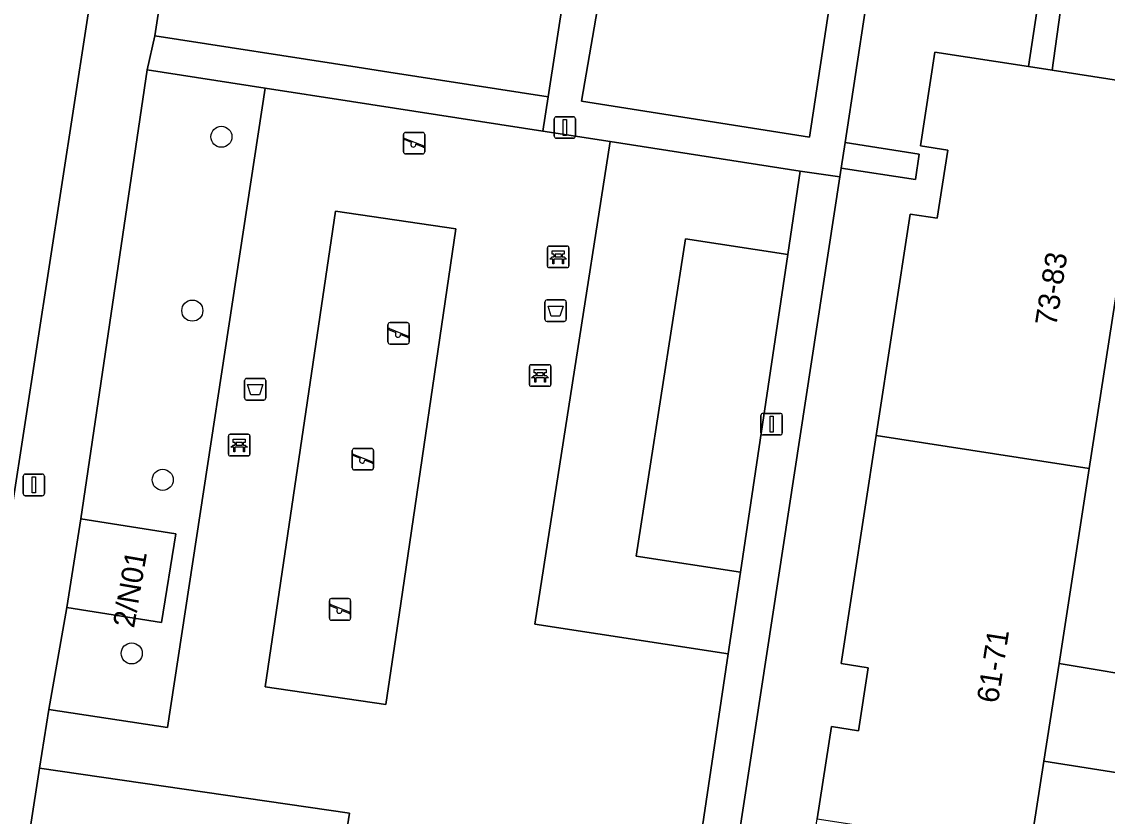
# Model space of a CAD drawing. Extents: x 161084 to 161928, y 385354 to 386522.
# Drawn here: x 161669.4 to 161719.8, y 385529 to 385565.9 of the extents above; entities that cross this region are included whole.
import ezdxf

# ---------------------------------------------------------------- set-up
doc = ezdxf.new("R2010")
doc.units = 0
for name, color, linetype in [('IMGEO_Afvalbak', 7, 'Continuous'), ('IMGEO_Bank', 7, 'Continuous'), ('IMGEO_Boom', 7, 'Continuous'), ('IMGEO_Groenvoorziening', 7, 'Continuous'), ('IMGEO_Lichtmast', 7, 'Continuous'), ('IMGEO_Pand', 7, 'Continuous'), ('IMGEO_Pand_nummerreeks', 7, 'Continuous'), ('IMGEO_Speelvoorziening', 7, 'Continuous'), ('IMGEO_Terreindeel_zand', 7, 'Continuous'), ('IMGEO_Voetpad_open', 7, 'Continuous')]:
    doc.layers.add(name, color=color, linetype=linetype)

msp = doc.modelspace()

# ---------------------------------------------------------------- linework, layer by layer
at = {"layer": 'IMGEO_Afvalbak'}
for p, q in [((161693.674, 385552.093), (161693.674, 385552.893)), ((161693.674, 385552.893), (161693.674, 385552.093)), ((161693.774, 385552.993), (161694.564, 385552.993)), ((161694.564, 385552.993), (161693.774, 385552.993)), ((161694.664, 385552.893), (161694.664, 385552.093)), ((161694.664, 385552.093), (161694.664, 385552.893)), ((161694.564, 385551.993), (161693.774, 385551.993)), ((161693.774, 385551.993), (161694.564, 385551.993)), ((161679.82, 385549.344), (161680.61, 385549.344)), ((161680.61, 385549.344), (161679.82, 385549.344)), ((161679.72, 385548.444), (161679.72, 385549.244)), ((161679.72, 385549.244), (161679.72, 385548.444)), ((161680.71, 385549.244), (161680.71, 385548.444)), ((161680.71, 385548.444), (161680.71, 385549.244)), ((161680.61, 385548.344), (161679.82, 385548.344)), ((161679.82, 385548.344), (161680.61, 385548.344))]:
    msp.add_line(p, q, dxfattribs=at)
for points in [[(161693.817, 385552.707), (161694.521, 385552.707), (161694.372, 385552.237), (161693.966, 385552.237), (161693.817, 385552.707)], [(161679.863, 385549.058), (161680.567, 385549.058), (161680.418, 385548.588), (161680.012, 385548.588), (161679.863, 385549.058)]]:
    msp.add_lwpolyline(points, dxfattribs=at)
for centre, start, end in [((161693.774, 385552.893), 90, 180), ((161693.774, 385552.893), 90, 180), ((161694.564, 385552.893), 0, 90), ((161694.564, 385552.893), 360, 90), ((161693.774, 385552.093), 180, 270), ((161693.774, 385552.093), 180, 270), ((161694.564, 385552.093), 270, 0), ((161694.564, 385552.093), 270, 0), ((161679.82, 385549.244), 90, 180), ((161679.82, 385549.244), 90, 180), ((161680.61, 385549.244), 0, 90), ((161680.61, 385549.244), 360, 90), ((161679.82, 385548.444), 180, 270), ((161679.82, 385548.444), 180, 270), ((161680.61, 385548.444), 270, 0), ((161680.61, 385548.444), 270, 0)]:
    msp.add_arc(centre, 0.1, start, end, dxfattribs=at)
at = {"layer": 'IMGEO_Bank'}
for p, q in [((161693.788, 385554.564), (161693.788, 385555.405)), ((161693.788, 385555.405), (161693.788, 385554.564)), ((161693.863, 385555.489), (161694.704, 385555.489)), ((161694.704, 385555.489), (161693.863, 385555.489)), ((161694.788, 385555.414), (161694.788, 385554.573)), ((161694.788, 385554.573), (161694.788, 385555.414)), ((161694.485, 385554.887), (161694.092, 385554.887)), ((161694.097, 385554.995), (161694.097, 385555.101)), ((161694.141, 385555.101), (161694.141, 385554.995)), ((161694.429, 385555.107), (161694.147, 385555.107)), ((161694.147, 385554.989), (161694.429, 385554.989)), ((161694.435, 385554.995), (161694.435, 385555.101)), ((161694.479, 385555.101), (161694.479, 385554.995)), ((161694.713, 385554.489), (161693.872, 385554.489)), ((161693.872, 385554.489), (161694.713, 385554.489)), ((161692.95, 385549.057), (161692.95, 385549.898)), ((161692.95, 385549.898), (161692.95, 385549.057)), ((161693.025, 385549.982), (161693.866, 385549.982)), ((161693.866, 385549.982), (161693.025, 385549.982)), ((161693.95, 385549.907), (161693.95, 385549.066)), ((161693.95, 385549.066), (161693.95, 385549.907)), ((161693.647, 385549.38), (161693.254, 385549.38)), ((161693.259, 385549.488), (161693.259, 385549.594)), ((161693.303, 385549.594), (161693.303, 385549.488)), ((161693.591, 385549.6), (161693.309, 385549.6)), ((161693.309, 385549.482), (161693.591, 385549.482)), ((161693.597, 385549.488), (161693.597, 385549.594)), ((161693.641, 385549.594), (161693.641, 385549.488)), ((161693.875, 385548.982), (161693.034, 385548.982)), ((161693.034, 385548.982), (161693.875, 385548.982)), ((161678.973, 385545.829), (161678.973, 385546.67)), ((161678.973, 385546.67), (161678.973, 385545.829)), ((161679.048, 385546.754), (161679.889, 385546.754)), ((161679.889, 385546.754), (161679.048, 385546.754)), ((161679.282, 385546.26), (161679.282, 385546.366)), ((161679.326, 385546.366), (161679.326, 385546.26)), ((161679.614, 385546.372), (161679.332, 385546.372)), ((161679.62, 385546.26), (161679.62, 385546.366)), ((161679.664, 385546.366), (161679.664, 385546.26)), ((161679.973, 385546.679), (161679.973, 385545.838)), ((161679.973, 385545.838), (161679.973, 385546.679)), ((161679.67, 385546.152), (161679.277, 385546.152)), ((161679.332, 385546.254), (161679.614, 385546.254)), ((161679.898, 385545.754), (161679.057, 385545.754)), ((161679.057, 385545.754), (161679.898, 385545.754))]:
    msp.add_line(p, q, dxfattribs=at)
for points in [[(161694.035, 385554.887), (161693.893, 385554.887), (161694.005, 385554.989), (161694.091, 385554.989)], [(161694.091, 385555.107), (161694.005, 385555.107), (161694.005, 385555.268), (161694.568, 385555.268), (161694.568, 385555.107), (161694.485, 385555.107)], [(161694.485, 385554.989), (161694.568, 385554.989), (161694.68, 385554.887), (161694.541, 385554.887)], [(161694.085, 385554.88), (161694.085, 385554.673), (161694.042, 385554.673), (161694.042, 385554.88)], [(161694.535, 385554.88), (161694.535, 385554.673), (161694.491, 385554.673), (161694.491, 385554.88)], [(161693.197, 385549.38), (161693.055, 385549.38), (161693.167, 385549.482), (161693.253, 385549.482)], [(161693.253, 385549.6), (161693.167, 385549.6), (161693.167, 385549.761), (161693.73, 385549.761), (161693.73, 385549.6), (161693.647, 385549.6)], [(161693.247, 385549.373), (161693.247, 385549.166), (161693.204, 385549.166), (161693.204, 385549.373)], [(161693.647, 385549.482), (161693.73, 385549.482), (161693.842, 385549.38), (161693.703, 385549.38)], [(161693.697, 385549.373), (161693.697, 385549.166), (161693.653, 385549.166), (161693.653, 385549.373)], [(161679.276, 385546.372), (161679.19, 385546.372), (161679.19, 385546.533), (161679.753, 385546.533), (161679.753, 385546.372), (161679.67, 385546.372)], [(161679.22, 385546.152), (161679.078, 385546.152), (161679.19, 385546.254), (161679.276, 385546.254)], [(161679.27, 385546.145), (161679.27, 385545.938), (161679.227, 385545.938), (161679.227, 385546.145)], [(161679.67, 385546.254), (161679.753, 385546.254), (161679.865, 385546.152), (161679.726, 385546.152)], [(161679.72, 385546.145), (161679.72, 385545.938), (161679.676, 385545.938), (161679.676, 385546.145)]]:
    msp.add_lwpolyline(points, dxfattribs=at)
for centre, radius, start, end in [((161693.866, 385555.411), 0.0779, 92.4484, 184.2845), ((161693.866, 385555.411), 0.0779, 92.4484, 184.2845), ((161694.71, 385555.411), 0.0779, 2.4484, 94.2845), ((161694.71, 385555.411), 0.0779, 2.4484, 94.2845), ((161694.035, 385554.88), 0.00671, 2.8957, 87.1043), ((161694.092, 385554.88), 0.00671, 92.8957, 177.1043), ((161694.09, 385555.1), 0.00671, 2.8957, 87.1043), ((161694.09, 385554.996), 0.00671, 272.8957, 357.1043), ((161694.147, 385555.1), 0.00671, 92.8957, 177.1043), ((161694.147, 385554.996), 0.00671, 182.8957, 267.1043), ((161694.429, 385555.1), 0.00671, 2.8957, 87.1043), ((161694.429, 385554.996), 0.00671, 272.8957, 357.1043), ((161694.486, 385555.1), 0.00671, 92.8957, 177.1043), ((161694.486, 385554.996), 0.00671, 182.8957, 267.1043), ((161694.484, 385554.88), 0.00671, 2.8957, 87.1043), ((161694.541, 385554.88), 0.00671, 92.8957, 177.1043), ((161693.866, 385554.567), 0.0779, 182.4484, 274.2845), ((161693.866, 385554.567), 0.0779, 182.4484, 274.2845), ((161694.71, 385554.567), 0.0779, 272.4484, 4.2845), ((161694.71, 385554.567), 0.0779, 272.4484, 4.2845), ((161693.028, 385549.904), 0.0779, 92.4484, 184.2845), ((161693.028, 385549.904), 0.0779, 92.4484, 184.2845), ((161693.872, 385549.904), 0.0779, 2.4484, 94.2845), ((161693.872, 385549.904), 0.0779, 2.4484, 94.2845), ((161693.197, 385549.373), 0.00671, 2.8957, 87.1043), ((161693.254, 385549.373), 0.00671, 92.8957, 177.1043), ((161693.252, 385549.593), 0.00671, 2.8957, 87.1043), ((161693.252, 385549.489), 0.00671, 272.8957, 357.1043), ((161693.309, 385549.593), 0.00671, 92.8957, 177.1043), ((161693.309, 385549.489), 0.00671, 182.8957, 267.1043), ((161693.591, 385549.593), 0.00671, 2.8957, 87.1043), ((161693.591, 385549.489), 0.00671, 272.8957, 357.1043), ((161693.648, 385549.593), 0.00671, 92.8957, 177.1043), ((161693.648, 385549.489), 0.00671, 182.8957, 267.1043), ((161693.646, 385549.373), 0.00671, 2.8957, 87.1043), ((161693.703, 385549.373), 0.00671, 92.8957, 177.1043), ((161693.028, 385549.06), 0.0779, 182.4484, 274.2845), ((161693.028, 385549.06), 0.0779, 182.4484, 274.2845), ((161693.872, 385549.06), 0.0779, 272.4484, 4.2845), ((161693.872, 385549.06), 0.0779, 272.4484, 4.2845), ((161679.051, 385546.676), 0.0779, 92.4484, 184.2845), ((161679.051, 385546.676), 0.0779, 92.4484, 184.2845), ((161679.275, 385546.365), 0.00671, 2.8957, 87.1043), ((161679.332, 385546.365), 0.00671, 92.8957, 177.1043), ((161679.614, 385546.365), 0.00671, 2.8957, 87.1043), ((161679.671, 385546.365), 0.00671, 92.8957, 177.1043), ((161679.895, 385546.676), 0.0779, 2.4484, 94.2845), ((161679.895, 385546.676), 0.0779, 2.4484, 94.2845), ((161679.051, 385545.832), 0.0779, 182.4484, 274.2845), ((161679.051, 385545.832), 0.0779, 182.4484, 274.2845), ((161679.22, 385546.145), 0.00671, 2.8957, 87.1043), ((161679.277, 385546.145), 0.00671, 92.8957, 177.1043), ((161679.275, 385546.261), 0.00671, 272.8957, 357.1043), ((161679.332, 385546.261), 0.00671, 182.8957, 267.1043), ((161679.614, 385546.261), 0.00671, 272.8957, 357.1043), ((161679.671, 385546.261), 0.00671, 182.8957, 267.1043), ((161679.669, 385546.145), 0.00671, 2.8957, 87.1043), ((161679.726, 385546.145), 0.00671, 92.8957, 177.1043), ((161679.895, 385545.832), 0.0779, 272.4484, 4.2845), ((161679.895, 385545.832), 0.0779, 272.4484, 4.2845)]:
    msp.add_arc(centre, radius, start, end, dxfattribs=at)
at = {"layer": 'IMGEO_Boom'}
for centre in [(161678.648, 385560.563), (161677.296, 385552.493), (161675.921, 385544.64), (161674.481, 385536.583)]:
    msp.add_circle(centre, 0.489, dxfattribs=at)
at = {"layer": 'IMGEO_Groenvoorziening'}
for points in [[(161676.732, 385572.916), (161675.558, 385565.255), (161684.945, 385563.794), (161686.427, 385563.563), (161693.826, 385562.411), (161695.311, 385572.063), (161695.631, 385574.145), (161695.859, 385575.628), (161698.823, 385594.901), (161698.975, 385595.889), (161700.619, 385606.575)], [(161662.849, 385544.418), (161663.304, 385544.268), (161668.139, 385543.516), (161668.928, 385543.394), (161672.366, 385565.674), (161674.034, 385576.484)], [(161727.809, 385567.017), (161717.914, 385568.577), (161717.223, 385563.649), (161721.705, 385562.959)], [(161723.62, 385530.521), (161716.851, 385531.587), (161716.2, 385527.382), (161715.451, 385522.539), (161722.403, 385521.5), (161723.407, 385522.236), (161724.441, 385529.408)]]:
    msp.add_lwpolyline(points, dxfattribs=at)
for points in [[(161707.395, 385570.046), (161696.989, 385571.64), (161695.367, 385562.217), (161705.954, 385560.553)], [(161708.692, 385535.916), (161707.425, 385536.11), (161709.051, 385546.696), (161710.63, 385556.976), (161711.897, 385556.782), (161712.382, 385559.945), (161711.116, 385560.139), (161711.784, 385564.487), (161716.127, 385563.818), (161716.872, 385568.738), (161709.056, 385569.786), (161707.615, 385560.292), (161711.058, 385559.763), (161710.876, 385558.577), (161707.433, 385559.106), (161707.374, 385558.705), (161702.137, 385524.559), (161705.558, 385523.963), (161706.317, 385528.904), (161706.975, 385533.185), (161708.242, 385532.991)], [(161670.626, 385533.985), (161676.151, 385533.143), (161680.682, 385562.825), (161675.205, 385563.675), (161672.117, 385542.833), (161676.525, 385542.134), (161675.871, 385538.012), (161671.463, 385538.711)], [(161702.756, 385540.358), (161697.915, 385541.104), (161700.208, 385555.827), (161704.956, 385555.095), (161705.534, 385558.969), (161696.695, 385560.34), (161693.207, 385537.945), (161702.189, 385536.561)], [(161702.756, 385540.358), (161704.956, 385555.095), (161700.208, 385555.827), (161697.915, 385541.104)], [(161717.551, 385536.113), (161722.189, 385535.345), (161724.894, 385553.02), (161720.279, 385553.742), (161718.953, 385545.171)], [(161668.88, 385522.726), (161683.871, 385520.546), (161684.952, 385527.492), (161684.345, 385527.588), (161684.594, 385529.164), (161670.203, 385531.256)]]:
    msp.add_lwpolyline(points, close=True, dxfattribs=at)
at = {"layer": 'IMGEO_Lichtmast'}
for p, q in [((161694.202, 385561.495), (161694.992, 385561.495)), ((161694.992, 385561.495), (161694.202, 385561.495)), ((161694.102, 385560.595), (161694.102, 385561.395)), ((161694.102, 385561.395), (161694.102, 385560.595)), ((161695.092, 385561.395), (161695.092, 385560.595)), ((161695.092, 385560.595), (161695.092, 385561.395)), ((161694.992, 385560.495), (161694.202, 385560.495)), ((161694.202, 385560.495), (161694.992, 385560.495)), ((161703.707, 385546.827), (161703.707, 385547.627)), ((161703.707, 385547.627), (161703.707, 385546.827)), ((161703.807, 385547.727), (161704.597, 385547.727)), ((161704.597, 385547.727), (161703.807, 385547.727)), ((161704.697, 385547.627), (161704.697, 385546.827)), ((161704.697, 385546.827), (161704.697, 385547.627)), ((161704.597, 385546.727), (161703.807, 385546.727)), ((161703.807, 385546.727), (161704.597, 385546.727)), ((161669.44, 385544.005), (161669.44, 385544.805)), ((161669.44, 385544.805), (161669.44, 385544.005)), ((161669.54, 385544.905), (161670.33, 385544.905)), ((161670.33, 385544.905), (161669.54, 385544.905)), ((161670.43, 385544.805), (161670.43, 385544.005)), ((161670.43, 385544.005), (161670.43, 385544.805)), ((161670.33, 385543.905), (161669.54, 385543.905)), ((161669.54, 385543.905), (161670.33, 385543.905))]:
    msp.add_line(p, q, dxfattribs=at)
for points in [[(161694.522, 385561.37), (161694.672, 385561.37), (161694.672, 385560.62), (161694.522, 385560.62), (161694.522, 385561.37)], [(161704.127, 385547.602), (161704.277, 385547.602), (161704.277, 385546.852), (161704.127, 385546.852), (161704.127, 385547.602)], [(161669.86, 385544.78), (161670.01, 385544.78), (161670.01, 385544.03), (161669.86, 385544.03), (161669.86, 385544.78)]]:
    msp.add_lwpolyline(points, dxfattribs=at)
for centre, start, end in [((161694.202, 385561.395), 90, 180), ((161694.202, 385561.395), 90, 180), ((161694.992, 385561.395), 0, 90), ((161694.992, 385561.395), 360, 90), ((161694.202, 385560.595), 180, 270), ((161694.202, 385560.595), 180, 270), ((161694.992, 385560.595), 270, 0), ((161694.992, 385560.595), 270, 0), ((161703.807, 385547.627), 90, 180), ((161703.807, 385547.627), 90, 180), ((161704.597, 385547.627), 0, 90), ((161704.597, 385547.627), 360, 90), ((161703.807, 385546.827), 180, 270), ((161703.807, 385546.827), 180, 270), ((161704.597, 385546.827), 270, 0), ((161704.597, 385546.827), 270, 0), ((161669.54, 385544.805), 90, 180), ((161669.54, 385544.805), 90, 180), ((161670.33, 385544.805), 0, 90), ((161670.33, 385544.805), 360, 90), ((161669.54, 385544.005), 180, 270), ((161669.54, 385544.005), 180, 270), ((161670.33, 385544.005), 270, 0), ((161670.33, 385544.005), 270, 0)]:
    msp.add_arc(centre, 0.1, start, end, dxfattribs=at)
at = {"layer": 'IMGEO_Pand'}
for points in [[(161716.127, 385563.818), (161711.784, 385564.487), (161711.116, 385560.139), (161712.382, 385559.945), (161711.897, 385556.782), (161710.63, 385556.976), (161709.051, 385546.696), (161718.953, 385545.171), (161720.279, 385553.742), (161720.973, 385558.225), (161721.705, 385562.959), (161717.223, 385563.649)], [(161718.953, 385545.171), (161709.051, 385546.696), (161707.425, 385536.11), (161708.692, 385535.916), (161708.242, 385532.991), (161706.975, 385533.185), (161706.317, 385528.904), (161716.2, 385527.382), (161716.851, 385531.587), (161717.551, 385536.113)], [(161671.463, 385538.711), (161675.871, 385538.012), (161676.525, 385542.134), (161672.117, 385542.833)]]:
    msp.add_lwpolyline(points, close=True, dxfattribs=at)
at = {"layer": 'IMGEO_Speelvoorziening'}
for p, q in [((161687.099, 385559.866), (161687.099, 385560.666)), ((161687.099, 385560.666), (161687.099, 385559.866)), ((161687.482, 385560.294), (161687.143, 385560.431)), ((161687.168, 385560.491), (161688.044, 385560.138)), ((161687.199, 385560.766), (161687.989, 385560.766)), ((161687.989, 385560.766), (161687.199, 385560.766)), ((161688.089, 385560.666), (161688.089, 385559.866)), ((161688.089, 385559.866), (161688.089, 385560.666)), ((161688.02, 385560.078), (161687.68, 385560.215)), ((161687.989, 385559.766), (161687.199, 385559.766)), ((161687.199, 385559.766), (161687.989, 385559.766)), ((161686.482, 385551.941), (161687.272, 385551.941)), ((161687.272, 385551.941), (161686.482, 385551.941)), ((161686.382, 385551.041), (161686.382, 385551.841)), ((161686.382, 385551.841), (161686.382, 385551.041)), ((161686.765, 385551.469), (161686.426, 385551.606)), ((161686.451, 385551.666), (161687.327, 385551.313)), ((161687.303, 385551.253), (161686.963, 385551.39)), ((161687.372, 385551.841), (161687.372, 385551.041)), ((161687.372, 385551.041), (161687.372, 385551.841)), ((161687.272, 385550.941), (161686.482, 385550.941)), ((161686.482, 385550.941), (161687.272, 385550.941)), ((161684.722, 385545.198), (161684.722, 385545.998)), ((161684.722, 385545.998), (161684.722, 385545.198)), ((161684.791, 385545.823), (161685.667, 385545.47)), ((161684.822, 385546.098), (161685.612, 385546.098)), ((161685.612, 385546.098), (161684.822, 385546.098)), ((161685.712, 385545.998), (161685.712, 385545.198)), ((161685.712, 385545.198), (161685.712, 385545.998)), ((161685.105, 385545.626), (161684.766, 385545.763)), ((161685.643, 385545.41), (161685.303, 385545.547)), ((161685.612, 385545.098), (161684.822, 385545.098)), ((161684.822, 385545.098), (161685.612, 385545.098)), ((161683.66, 385538.226), (161683.66, 385539.026)), ((161683.66, 385539.026), (161683.66, 385538.226)), ((161684.043, 385538.654), (161683.704, 385538.791)), ((161683.729, 385538.851), (161684.605, 385538.498)), ((161683.76, 385539.126), (161684.55, 385539.126)), ((161684.55, 385539.126), (161683.76, 385539.126)), ((161684.65, 385539.026), (161684.65, 385538.226)), ((161684.65, 385538.226), (161684.65, 385539.026)), ((161684.581, 385538.438), (161684.241, 385538.575)), ((161684.55, 385538.126), (161683.76, 385538.126)), ((161683.76, 385538.126), (161684.55, 385538.126))]:
    msp.add_line(p, q, dxfattribs=at)
for centre, radius, start, end in [((161687.199, 385560.666), 0.1, 90, 180), ((161687.199, 385560.666), 0.1, 90, 180), ((161687.156, 385560.461), 0.0327, 68.078, 248.078), ((161687.989, 385560.666), 0.1, 0, 90), ((161687.989, 385560.666), 0.1, 360, 90), ((161687.561, 385560.204), 0.12, 130.9928, 5.1632), ((161688.032, 385560.108), 0.0327, 248.078, 68.078), ((161687.199, 385559.866), 0.1, 180, 270), ((161687.199, 385559.866), 0.1, 180, 270), ((161687.989, 385559.866), 0.1, 270, 0), ((161687.989, 385559.866), 0.1, 270, 0), ((161686.482, 385551.841), 0.1, 90, 180), ((161686.482, 385551.841), 0.1, 90, 180), ((161687.272, 385551.841), 0.1, 0, 90), ((161687.272, 385551.841), 0.1, 360, 90), ((161686.439, 385551.636), 0.0327, 68.078, 248.078), ((161686.844, 385551.379), 0.12, 130.9928, 5.1632), ((161686.482, 385551.041), 0.1, 180, 270), ((161686.482, 385551.041), 0.1, 180, 270), ((161687.272, 385551.041), 0.1, 270, 0), ((161687.272, 385551.041), 0.1, 270, 0), ((161687.315, 385551.283), 0.0327, 248.078, 68.078), ((161684.822, 385545.998), 0.1, 90, 180), ((161684.822, 385545.998), 0.1, 90, 180), ((161684.779, 385545.793), 0.0327, 68.078, 248.078), ((161685.612, 385545.998), 0.1, 0, 90), ((161685.612, 385545.998), 0.1, 360, 90), ((161685.184, 385545.536), 0.12, 130.9928, 5.1632), ((161685.655, 385545.44), 0.0327, 248.078, 68.078), ((161684.822, 385545.198), 0.1, 180, 270), ((161684.822, 385545.198), 0.1, 180, 270), ((161685.612, 385545.198), 0.1, 270, 0), ((161685.612, 385545.198), 0.1, 270, 0), ((161683.76, 385539.026), 0.1, 90, 180), ((161683.76, 385539.026), 0.1, 90, 180), ((161683.717, 385538.821), 0.0327, 68.078, 248.078), ((161684.55, 385539.026), 0.1, 0, 90), ((161684.55, 385539.026), 0.1, 360, 90), ((161684.122, 385538.564), 0.12, 130.9928, 5.1632), ((161684.593, 385538.468), 0.0327, 248.078, 68.078), ((161683.76, 385538.226), 0.1, 180, 270), ((161683.76, 385538.226), 0.1, 180, 270), ((161684.55, 385538.226), 0.1, 270, 0), ((161684.55, 385538.226), 0.1, 270, 0)]:
    msp.add_arc(centre, radius, start, end, dxfattribs=at)
at = {"layer": 'IMGEO_Terreindeel_zand'}
msp.add_lwpolyline([(161686.977, 385538.905), (161689.542, 385556.286), (161683.94, 385557.112), (161680.682, 385535.036), (161686.284, 385534.21)], close=True, dxfattribs=at)
at = {"layer": 'IMGEO_Voetpad_open'}
for points in [[(161682.306, 385629.936), (161677.325, 385598.393), (161675.404, 385586.149), (161674.661, 385580.545), (161674.034, 385576.484), (161672.366, 385565.674), (161668.928, 385543.394), (161668.239, 385538.924), (161668.116, 385538.133), (161667.803, 385536.052), (161663.625, 385508.283), (161661.817, 385496.26), (161658.19, 385472.711), (161656.38, 385460.922), (161656.38, 385460.904), (161655.699, 385456.628), (161655.683, 385456.575), (161655.028, 385452.288)], [(161675.205, 385563.675), (161675.558, 385565.255), (161676.732, 385572.916), (161677.419, 385577.388), (161680.318, 385596.144), (161681.062, 385601.073), (161682.526, 385610.747), (161683.06, 385614.032), (161684.287, 385621.684), (161684.764, 385624.801), (161685.325, 385629.197)], [(161704.883, 385608.326), (161704.848, 385608.336), (161700.995, 385608.885), (161700.619, 385606.575), (161698.975, 385595.889), (161698.823, 385594.901), (161695.859, 385575.628), (161695.631, 385574.145), (161695.311, 385572.063), (161693.826, 385562.411), (161693.582, 385560.823), (161696.695, 385560.34), (161705.534, 385558.969), (161707.374, 385558.705), (161707.433, 385559.106), (161707.615, 385560.292), (161709.056, 385569.786)], [(161656.719, 385442.697), (161665.355, 385500), (161668.88, 385522.726), (161670.203, 385531.256), (161670.626, 385533.985), (161671.463, 385538.711), (161672.117, 385542.833), (161675.205, 385563.675)], [(161707.374, 385558.705), (161705.534, 385558.969), (161704.956, 385555.095), (161702.756, 385540.358), (161702.189, 385536.561), (161700.47, 385525.043), (161697.457, 385504.857), (161696.732, 385500), (161694.277, 385483.736), (161687.355, 385437.87), (161686.853, 385434.542)], [(161656.268, 385438.891), (161655.732, 385434.651), (161668.914, 385432.617), (161670.074, 385432.438), (161679.607, 385430.967), (161687.795, 385429.703), (161688.497, 385434.107), (161689.58, 385441.334), (161690.48, 385447.333), (161691.266, 385452.58), (161691.376, 385453.312), (161692.797, 385462.794), (161692.94, 385463.744), (161696.643, 385488.449), (161696.796, 385489.473), (161698.167, 385498.626), (161698.304, 385499.531), (161698.375, 385500), (161701.928, 385523.472), (161702.137, 385524.559), (161707.374, 385558.705)], [(161724.361, 385534.985), (161722.189, 385535.345), (161717.551, 385536.113), (161716.851, 385531.587), (161723.62, 385530.521)]]:
    msp.add_lwpolyline(points, dxfattribs=at)
for points in [[(161707.395, 385570.046), (161705.954, 385560.553), (161695.367, 385562.217), (161696.989, 385571.64)], [(161716.872, 385568.738), (161716.127, 385563.818), (161717.223, 385563.649), (161717.914, 385568.577)], [(161686.427, 385563.563), (161684.945, 385563.794), (161675.558, 385565.255), (161675.205, 385563.675), (161680.682, 385562.825), (161684.691, 385562.203), (161693.582, 385560.823), (161693.826, 385562.411)], [(161696.695, 385560.34), (161693.582, 385560.823), (161684.691, 385562.203), (161680.682, 385562.825), (161676.151, 385533.143), (161670.626, 385533.985), (161670.203, 385531.256), (161684.594, 385529.164), (161684.345, 385527.588), (161684.952, 385527.492), (161700.47, 385525.043), (161702.189, 385536.561), (161693.207, 385537.945)], [(161707.615, 385560.292), (161707.433, 385559.106), (161710.876, 385558.577), (161711.058, 385559.763)], [(161686.977, 385538.905), (161686.284, 385534.21), (161680.682, 385535.036), (161683.94, 385557.112), (161689.542, 385556.286)]]:
    msp.add_lwpolyline(points, close=True, dxfattribs=at)

# ---------------------------------------------------------------- texts
at = {"layer": 'IMGEO_Pand_nummerreeks'}
for s, rotation, p in [('73-83', 81.2044, (161717.419, 385551.737)), ('2/N01', 80.1691, (161674.586, 385537.728)), ('61-71', 81.2049, (161714.711, 385534.238))]:
    msp.add_text(s, height=1, rotation=rotation, dxfattribs=at).set_placement(p)

doc.saveas('drawing.dxf')
